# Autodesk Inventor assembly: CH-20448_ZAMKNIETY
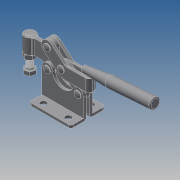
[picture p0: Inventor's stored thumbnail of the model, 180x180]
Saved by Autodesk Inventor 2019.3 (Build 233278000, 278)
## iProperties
Company: ·L?¤¤?
Created: 2010-06
Part Number: CH-20448_ZAMKNIETY
Material: Ogólny
Description: STEP AP203
Document SubType Name: Assembly
Designer: CADENGINEERING4
Sending System: SolidWorks 2005179
Preprocessor: SwSTEP 2.0
Title: CH-20448.STEP
Author: ·L?¥Î?
Revision Number: ANY
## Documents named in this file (8)
- E:\STRONA\Horizontal toggle clamp\CH-20448\CH-20448_ZAMKNIETY.iam
- E:\STRONA\Horizontal toggle clamp\CH-20448\20448-05___.ipt
- E:\STRONA\Horizontal toggle clamp\CH-20448\20448-02____ûV¡ø_.ipt
- E:\STRONA\Horizontal toggle clamp\CH-20448\M10___.ipt
- E:\STRONA\Horizontal toggle clamp\CH-20448\20448-03___.ipt
- E:\STRONA\Horizontal toggle clamp\CH-20448\CH-FC-105015___.ipt
- E:\STRONA\Horizontal toggle clamp\CH-20448\20448-01___.ipt
- E:\STRONA\Horizontal toggle clamp\CH-20448\20448-04____ûV¡ø_.ipt
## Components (10 placed, 10 different names)
1. 20448-05_??_1 — Zestawiające:6, Zestawiające:7
2. 20448-02_??<ûV¡ø>_2 — Równoległe:1, Zestawiające:2, Zestawiające:3, Zestawiające:12, Zestawiające:13, Zestawiające:16
3. M10_??_3 — Zestawiające:1, Zestawiające:2
4. 20448-03_??_4 — Zestawiające:4, Zestawiające:5, Zestawiające:8, Zestawiające:9
5. 20448-05_??_5 — Zestawiające:17, Zestawiające:18
6. CH-FC-105015_??_6 — Równoległe:1, Zestawiające:1, Zestawiające:3
7. 20448-01_??_7 — Zestawiające:4, Zestawiające:5, Zestawiające:6, Zestawiające:7, Zestawiające:12, Zestawiające:13, Zestawiające:14, Zestawiające:15, Przejściowe:1
8. 20448-05_??_8 — Zestawiające:10, Zestawiające:11
9. 20448-04_??<ûV¡ø>_9 — Zestawiające:8, Zestawiające:9, Zestawiające:10, Zestawiające:11, Zestawiające:16, Zestawiające:17, Zestawiające:18, Przejściowe:1
10. 20448-05_??_10 — Zestawiające:14, Zestawiające:15
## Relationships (20: Mate 18, Flush 1, Transitional 1)
- Równoległe:1 [Flush]: 20448-02_??<ûV¡ø>_2 ↔ CH-FC-105015_??_6
- Zestawiające:1 [Mate]: M10_??_3 ↔ CH-FC-105015_??_6
- Zestawiające:2 [Mate]: 20448-02_??<ûV¡ø>_2 ↔ M10_??_3
- Zestawiające:3 [Mate]: 20448-02_??<ûV¡ø>_2 ↔ CH-FC-105015_??_6
- Zestawiające:4 [Mate]: 20448-03_??_4 ↔ 20448-01_??_7
- Zestawiające:5 [Mate]: 20448-03_??_4 ↔ 20448-01_??_7
- Zestawiające:6 [Mate]: 20448-05_??_1 ↔ 20448-01_??_7
- Zestawiające:7 [Mate]: 20448-05_??_1 ↔ 20448-01_??_7
- Zestawiające:8 [Mate]: 20448-03_??_4 ↔ 20448-04_??<ûV¡ø>_9
- Zestawiające:9 [Mate]: 20448-03_??_4 ↔ 20448-04_??<ûV¡ø>_9
- Zestawiające:10 [Mate]: 20448-05_??_8 ↔ 20448-04_??<ûV¡ø>_9
- Zestawiające:11 [Mate]: 20448-05_??_8 ↔ 20448-04_??<ûV¡ø>_9
- Zestawiające:12 [Mate]: 20448-02_??<ûV¡ø>_2 ↔ 20448-01_??_7
- Zestawiające:13 [Mate]: 20448-02_??<ûV¡ø>_2 ↔ 20448-01_??_7
- Zestawiające:14 [Mate]: 20448-01_??_7 ↔ 20448-05_??_10
- Zestawiające:15 [Mate]: 20448-01_??_7 ↔ 20448-05_??_10
- Zestawiające:16 [Mate]: 20448-02_??<ûV¡ø>_2 ↔ 20448-04_??<ûV¡ø>_9
- Zestawiające:17 [Mate]: 20448-05_??_5 ↔ 20448-04_??<ûV¡ø>_9
- Zestawiające:18 [Mate]: 20448-05_??_5 ↔ 20448-04_??<ûV¡ø>_9
- Przejściowe:1 [Transitional]: 20448-01_??_7 ↔ 20448-04_??<ûV¡ø>_9
